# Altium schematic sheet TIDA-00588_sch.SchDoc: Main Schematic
size 431 x 279 mm; Date: Not shown in title block; ApprovedBy: Not shown in title block; CheckedBy: Not shown in title block; Author: Not shown in title block; CompanyName: Not shown in title block; DrawnBy: Gordon Varney; Engineer: Gordon Varney; Organization: Not shown in title block; Address1: Not shown in title block; Address2: Not shown in title block; Address3: Not shown in title block; Address4: Not shown in title block; DocumentNumber: 1; Revision: Use project parameter SCH_Rev; SheetNumber: 2; SheetTotal: 3; PageSetup: Record=PageOptions¦CenterHorizontal=True¦CenterVertical=True¦PrintScale=0.64¦XCorrection=1.00¦YCorrection=1.00¦PrintKind=0¦BorderSize=5000000¦LeftOffset=0¦BottomOffset=0¦Orientation=2¦PaperLength=1000¦PaperWidth=1000¦Scale=100¦PaperSource=15¦PrintQuality=600¦MediaType=1¦DitherType=10¦PrintScaleMode=1¦PaperKind=Letter
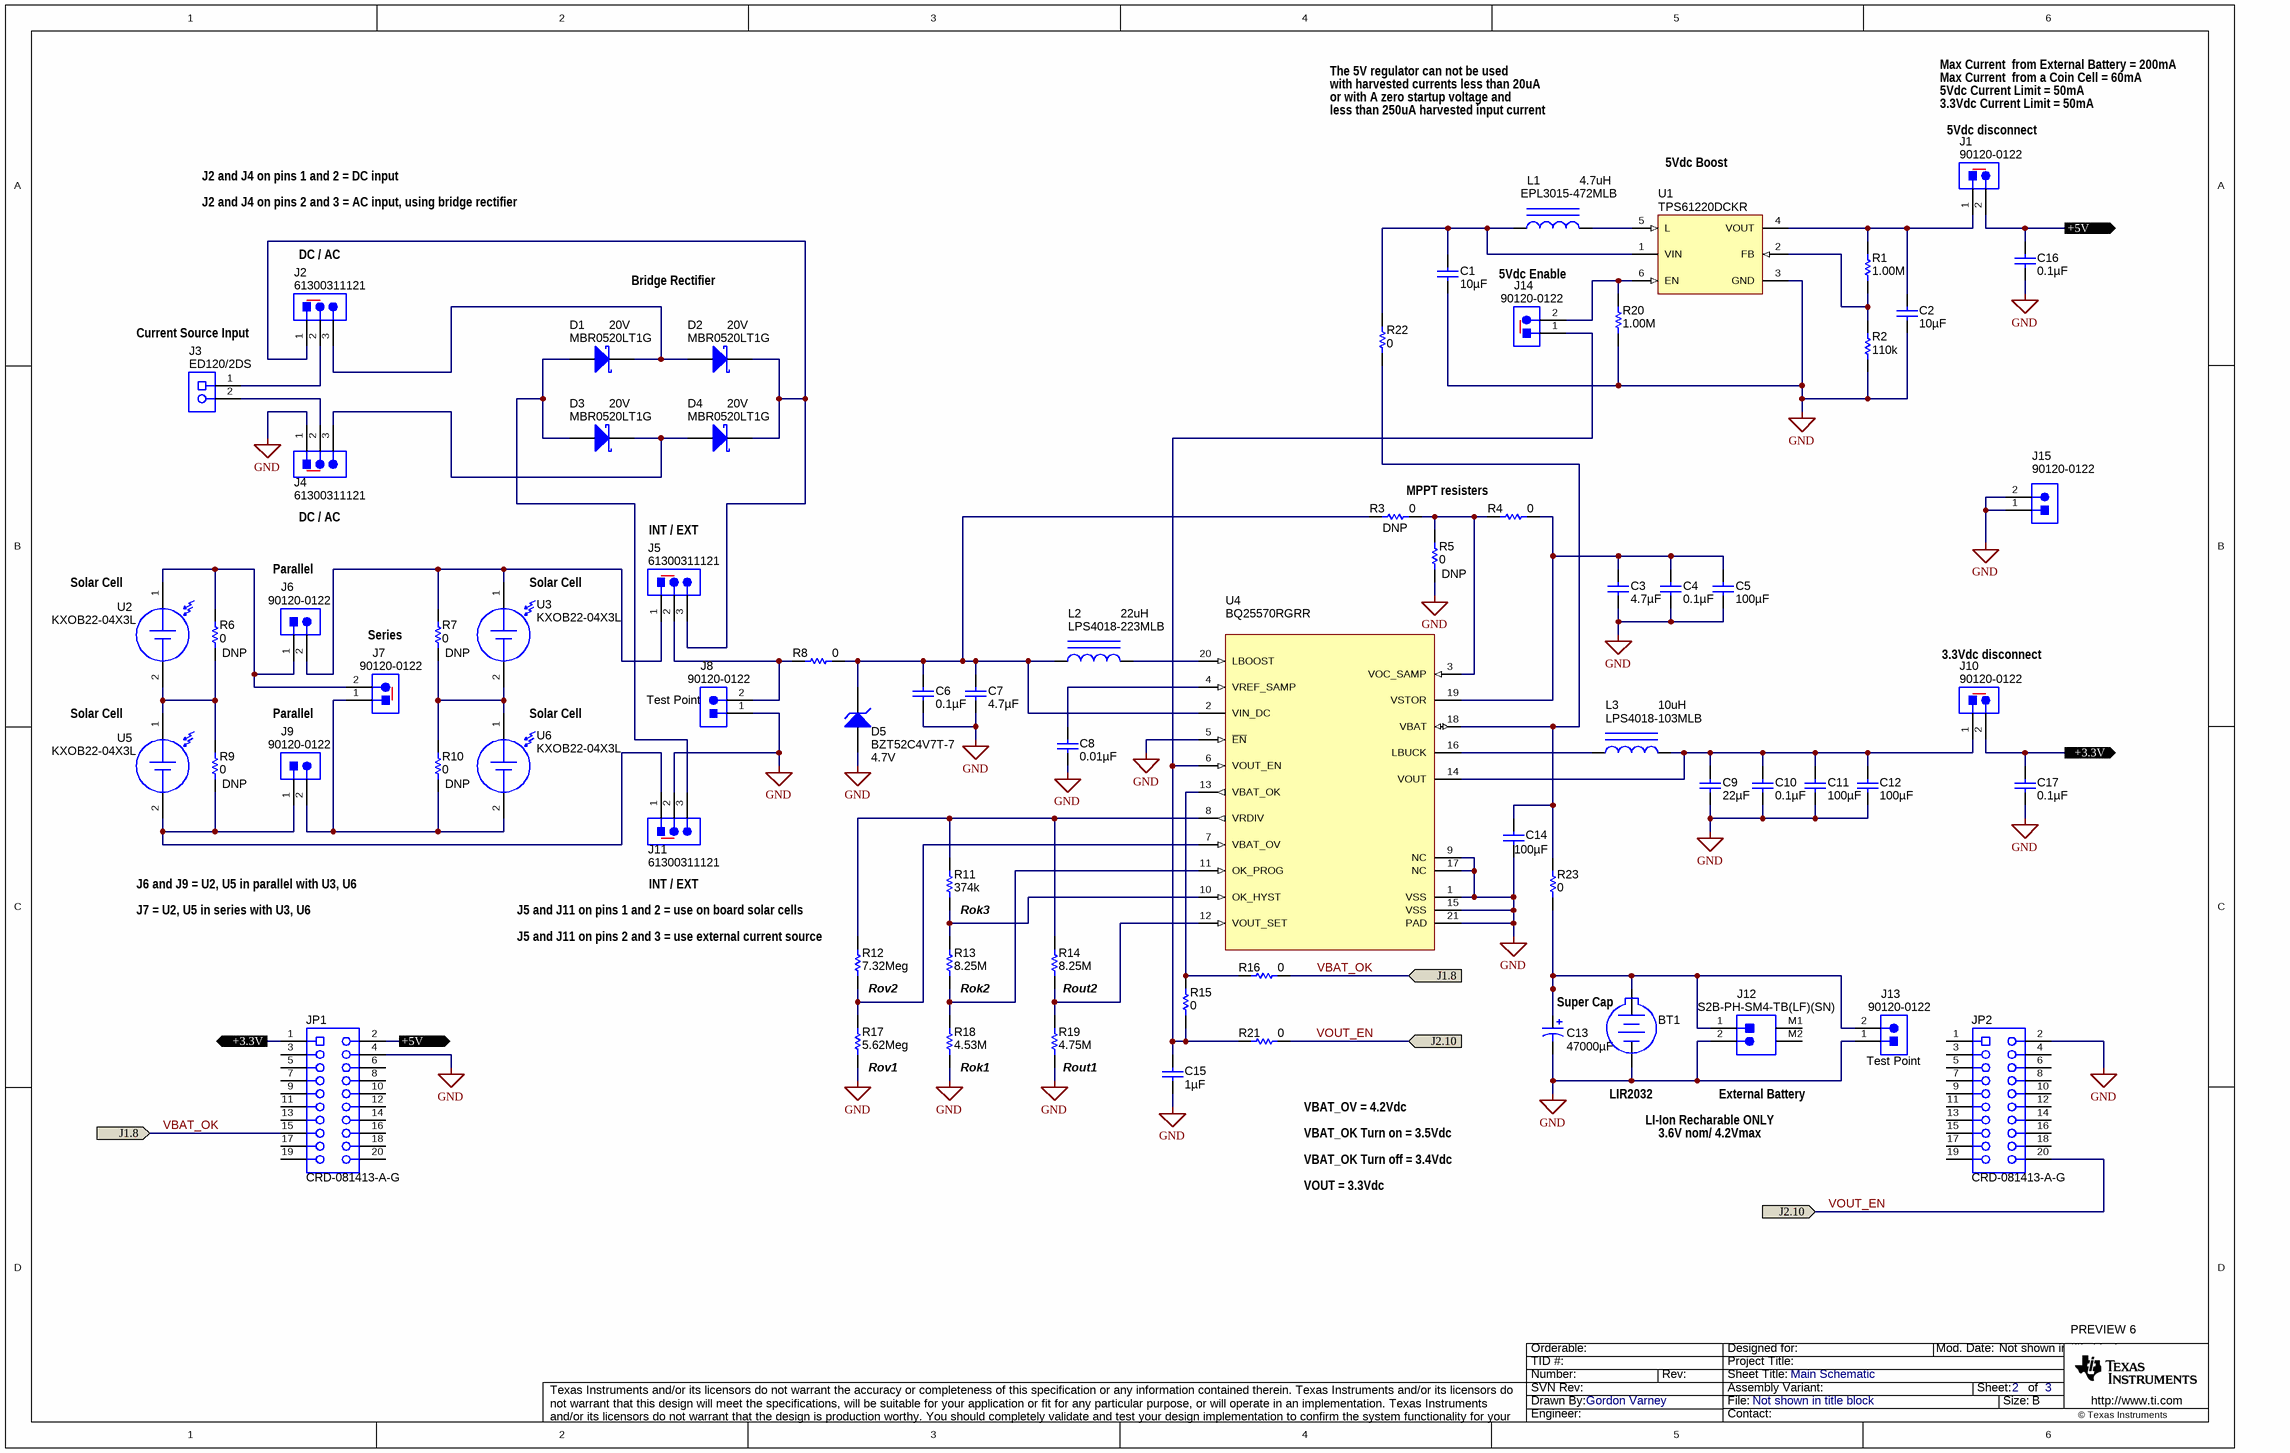
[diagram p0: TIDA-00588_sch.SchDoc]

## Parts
BT1  BS-7  [BAT_BS-7]  (value not drawn)
C1  ValueDisplayed: 10µF  [0805_HV]  (hidden comment: GRM21BR61A106KE19L)
C2  ValueDisplayed: 10µF  [0805_HV]  (hidden comment: GRM21BR61A106KE19L)
C3  ValueDisplayed: 4.7µF  [0402]  (hidden comment: C1005X5R0J475M050BC)
C4  ValueDisplayed: 0.1µF  [0402]  (hidden comment: GRM155R71A104KA01D)
C5  ValueDisplayed: 100µF  [1210]  (hidden comment: C1210C107M9PACTU)
C6  ValueDisplayed: 0.1µF  [0402]  (hidden comment: GRM155R71A104KA01D)
C7  ValueDisplayed: 4.7µF  [0402]  (hidden comment: C1005X5R0J475M050BC)
C8  ValueDisplayed: 0.01µF  [0402]  (hidden comment: GRM155R61A103KA01D)
C9  ValueDisplayed: 22µF  [0603]  (hidden comment: CL10A226MP8NUNE)
C10  ValueDisplayed: 0.1µF  [0402]  (hidden comment: GRM155R71A104KA01D)
C11  ValueDisplayed: 100µF  [1210]  (hidden comment: C1210C107M9PACTU)
C12  ValueDisplayed: 100µF  [1210]  (hidden comment: C1210C107M9PACTU)
C13  ValueDisplayed: 47000µF  [DX-H_1150x500]  (hidden comment: DX-5R5H473U)
C14  ValueDisplayed: 100µF  [1210]  (hidden comment: C1210C107M9PACTU)
C15  ValueDisplayed: 1µF  [0402]  (hidden comment: C1005X5R0J105M)
C16  ValueDisplayed: 0.1µF  [0402]  (hidden comment: GRM155R71A104KA01D)
C17  ValueDisplayed: 0.1µF  [0402]  (hidden comment: GRM155R71A104KA01D)
D1  MBR0520LT1G  value 20V  [SOD-123]
D2  MBR0520LT1G  value 20V  [SOD-123]
D3  MBR0520LT1G  value 20V  [SOD-123]
D4  MBR0520LT1G  value 20V  [SOD-123]
D5  BZT52C4V7T-7  value 4.7V  [SOD-523]
J1  90120-0122  [CONN_90120-0122]
J2  61300311121  [WURTH_61300311121]
J3  ED120/2DS  [CONN_ED120-2DS]
J4  61300311121  [WURTH_61300311121]
J5  61300311121  [WURTH_61300311121]
J6  90120-0122  [CONN_90120-0122]
J7  90120-0122  [CONN_90120-0122]
J8  90120-0122  [CONN_90120-0122]
J9  90120-0122  [CONN_90120-0122]
J10  90120-0122  [CONN_90120-0122]
J11  61300311121  [WURTH_61300311121]
J12  S2B-PH-SM4-TB(LF)(SN)  [JST_S2B-PH-SM4-TB]
J13  90120-0122  [CONN_90120-0122]
J14  90120-0122  [CONN_90120-0122]
J15  90120-0122  [CONN_90120-0122]
JP1  CRD-081413-A-G  [Major_CRD-081413-A-x]
JP2  CRD-081413-A-G  [Major_CRD-081413-A-x]
L1  EPL3015-472MLB  value 4.7uH  [EPL3015]
L2  LPS4018-223MLB  value 22uH  [LPS4018]
L3  LPS4018-103MLB  value 10uH  [LPS4018]
R1  ValueDisplayed: 1.00M  [0603]  (hidden comment: CRCW06031M00FKEA)
R2  ValueDisplayed: 110k  [0603]  (hidden comment: CRCW0603110KFKEA)
R3  value 0  Res_ohm: DNP  [0603]  (hidden comment: ERJ-3GEY0R00V)
R4  value 0  [0603]  (hidden comment: ERJ-3GEY0R00V)
R5  value 0  Res_ohm: DNP  [0603]  (hidden comment: ERJ-3GEY0R00V)
R6  value 0  ValueDisplayed: DNP  [0805_HV]  (hidden comment: CRCW08050000Z0EA)
R7  value 0  ValueDisplayed: DNP  [0805_HV]  (hidden comment: CRCW08050000Z0EA)
R8  value 0  [0603]  (hidden comment: ERJ-3GEY0R00V)
R9  value 0  ValueDisplayed: DNP  [0805_HV]  (hidden comment: CRCW08050000Z0EA)
R10  value 0  ValueDisplayed: DNP  [0805_HV]  (hidden comment: CRCW08050000Z0EA)
R11  ValueDisplayed: 374k  [0603]  (hidden comment: CRCW0603374KFKEA)
R12  value 7.32Meg  [0603]  (hidden comment: CRCW06037M32FKEA)
R13  ValueDisplayed: 8.25M  [0603]  (hidden comment: CRCW06038M25FKEA)
R14  ValueDisplayed: 8.25M  [0603]  (hidden comment: CRCW06038M25FKEA)
R15  value 0  [0603]  (hidden comment: ERJ-3GEY0R00V)
R16  value 0  [0603]  (hidden comment: ERJ-3GEY0R00V)
R17  value 5.62Meg  [0603]  (hidden comment: CRCW06035M62FKEA)
R18  ValueDisplayed: 4.53M  [0603]  (hidden comment: CRCW06034M53FKEA)
R19  ValueDisplayed: 4.75M  [0603]  (hidden comment: CRCW06034M75FKEA)
R20  ValueDisplayed: 1.00M  [0603]  (hidden comment: CRCW06031M00FKEA)
R21  value 0  [0603]  (hidden comment: ERJ-3GEY0R00V)
R22  value 0  [0603]  (hidden comment: ERJ-3GEY0R00V)
R23  value 0  [0603]  (hidden comment: ERJ-3GEY0R00V)
U1  TPS61220DCKR  [DCK0006A_N]
U2  KXOB22-04X3L  [KXOB22-04X3]
U3  KXOB22-04X3L  [KXOB22-04X3]
U4  BQ25570RGRR  [RGR0020A]
U5  KXOB22-04X3L  [KXOB22-04X3]
U6  KXOB22-04X3L  [KXOB22-04X3]

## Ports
+3.3V, +5V, J1.8, J2.10

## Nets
GND: BT1.2(-) C1.1 C2.2 C3.2 C4.2 C5.2 C6.2 C7.2 C8.2 C9.2 C10.2 C11.2 C12.2 C13.2(-) C14.2 C15.2 C16.2 C17.2 D5.2(A) J4.1 J8.1 J11.2 J12.2 J13.1 J15.1 J15.2 JP1.4 JP2.2 R2.1 R5.1 R17.1 R18.1 R19.2 R20.1 U1.3(GND) U4.1(VSS) U4.5(~{EN}) U4.9(NC) U4.15(VSS) U4.17(NC) U4.21(PAD)
+3.3V: C17.1 J10.2 JP1.1 ; port +3.3V
+5V: C16.1 J1.2 JP1.2 ; port +5V
VBAT_OK: JP1.15 R16.2 ; port J1.8
VOUT_EN: JP2.20 R21.2 ; port J2.10
NetBT1_1: BT1.1(+) C13.1(+) J12.1 J13.2 R23.1
NetC1_2: C1.2 L1.1 R22.2 U1.1(VIN)
NetC2_1: C2.1 J1.1 R1.2 U1.4(VOUT)
NetC3_1: C3.1 C4.1 C5.1 R4.2 U4.19(VSTOR)
NetC6_1: C6.1 C7.1 D5.1(K) L2.1 R3.1 R8.2 U4.2(VIN_DC)
NetC8_1: C8.1 U4.4(VREF_SAMP)
NetC9_1: C9.1 C10.1 C11.1 C12.1 J10.1 L3.2 U4.14(VOUT)
NetC14_1: C14.1 R22.1 R23.2 U4.18(VBAT)
NetC15_1: C15.1 J14.1 R15.1 R21.1 U4.6(VOUT_EN)
NetD1_1: D1.1(K) D2.2(A) J2.3
NetD1_2: D1.2(A) D3.2(A) J11.3
NetD2_1: D2.1(K) D4.1(K) J2.1 J5.3
NetD3_1: D3.1(K) D4.2(A) J4.3
NetJ2_2: J2.2 J3.1
NetJ3_2: J3.2 J4.2
NetJ5_1: J5.1 J6.2 R7.2 U3.1(+)
NetJ5_2: J5.2 J8.2 R8.1
NetJ6_1: J6.1 J7.2 R6.2 U2.1(+)
NetJ7_1: J7.1 J9.2 R10.1 U6.2(-)
NetJ9_1: J9.1 J11.1 R9.1 U5.2(-)
NetJ14_2: J14.2 R20.2 U1.6(EN)
NetL1_2: L1.2 U1.5(L)
NetL2_2: L2.2 U4.20(LBOOST)
NetL3_1: L3.1 U4.16(LBUCK)
NetR1_1: R1.1 R2.2 U1.2(FB)
NetR3_2: R3.2 R4.1 R5.2 U4.3(VOC_SAMP)
NetR6_1: R6.1 R9.2 U2.2(-) U5.1(+)
NetR7_1: R7.1 R10.2 U3.2(-) U6.1(+)
NetR11_1: R11.1 R13.2 U4.10(OK_HYST)
NetR11_2: R11.2 R12.2 R14.2 U4.8(VRDIV)
NetR12_1: R12.1 R17.2 U4.7(VBAT_OV)
NetR13_1: R13.1 R18.2 U4.11(OK_PROG)
NetR14_1: R14.1 R19.1 U4.12(VOUT_SET)
NetR15_2: R15.2 R16.1 U4.13(VBAT_OK)

Not connected (* = marked no-connect by the designer): J12 M1 M2; JP1 3 5 6 7 8 9 10 11 12 13 14 16 17 18 19 20; JP2 1 3 4 5 6 7 8 9 10 11 12 13 14 15 16 17 18 19

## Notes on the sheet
- with harvested currents less than 20uA
- The 5V regulator can not be used
- or with A zero startup voltage and
- Max Current  from External Battery = 200mA
- 5Vdc Current Limit = 50mA
- Max Current  from a Coin Cell = 60mA
- less than 250uA harvested input current
- 5Vdc Boost
- 3.3Vdc Current Limit = 50mA
- (near J1) 5Vdc disconnect
- J2 and J4 on pins 1 and 2 = DC input
- J2 and J4 on pins 2 and 3 = AC input, using bridge rectifier
- DC / AC
- Bridge Rectifier
- 5Vdc Enable
- Current Source Input
- MPPT resisters
- INT / EXT
- (near U2) Solar Cell
- Parallel
- (near U3) Solar Cell
- Series
- (near J10) 3.3Vdc disconnect
- Solar Cell
- (near U6) Solar Cell
- (near J8) Test Point
- J6 and J9 = U2, U5 in parallel with U3, U6
- J7 = U2, U5 in series with U3, U6
- (near R12) J5 and J11 on pins 1 and 2 = use on board solar cells
- (near R12) J5 and J11 on pins 2 and 3 = use external current source
- (near R11) Rok3
- (near R12) Rov2
- (near R13) Rok2
- (near R14) Rout2
- Super Cap
- (near R17) Rov1
- (near R18) Rok1
- (near R19) Rout1
- (near J13) Test Point
- VBAT_OV = 4.2Vdc
- VBAT_OK Turn on = 3.5Vdc
- LIR2032
- LI-Ion Recharable ONLY
- 3.6V nom/ 4.2Vmax
- (near J12) External Battery
- VBAT_OK Turn off = 3.4Vdc
- VOUT = 3.3Vdc
- PREVIEW 6

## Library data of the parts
BT1 = BS-7: Battery Holder, CR2032, Retainer clip, TH; Manufacturer: Memory Protection Devices; SymbolCreator: a0412235
C1 C2 = GRM21BR61A106KE19L: CAP, CERM, 10 µF, 10 V, +/- 10%, X5R, 0805; Manufacturer: MuRata; Polarized: N; CompType: Capacitor; Value: 10uF; U/M: EA; Cap_F: 0.00001; Tolerance_%: 10; ESR_ohm: 0.002; Value1: 0.002 ohm; Value2: 10V; TaMin_C: -55; TaMax_C: 85; Cap_Case: 0805
C3 C7 = C1005X5R0J475M050BC: CAP, CERM, 4.7 µF, 6.3 V, +/- 20%, X5R, 0402; Manufacturer: TDK; Polarized: N; CompType: Capacitor; Value: 4.7uF; U/M: EA; Cap_F: 0.0000047; Tolerance_%: 20; Value1: Unknown; VDC_V: 6.3; Value2: 6.3V; TaMin_C: -55; TaMax_C: 85
C4 C6 C10 C16 C17 = GRM155R71A104KA01D: CAP, CERM, 0.1 µF, 10 V, +/- 10%, X7R, 0402; Manufacturer: MuRata; Polarized: N; CompType: Capacitor; Value: 0.1uF; U/M: EA; Cap_F: 0.0000001; Tolerance_%: 10; Value1: Unknown; Value2: 10V; TaMin_C: -55; TaMax_C: 125
C5 C11 C12 C14 = C1210C107M9PACTU: CAP, CERM, 100 µF, 6.3 V, +/- 20%, X5R, 1210; Manufacturer: Kemet; Polarized: N; CompType: Capacitor; Value: 100uF; U/M: EA; Cap_F: 0.0001; Tolerance_%: 20; Value1: Unknown; VDC_V: 6.3; Value2: 6.3V; TaMin_C: -55; TaMax_C: 85
C8 = GRM155R61A103KA01D: CAP, CERM, 0.01 µF, 10 V, +/- 10%, X5R, 0402; Manufacturer: MuRata; Polarized: N; CompType: Capacitor; Value: 0.01uF; U/M: EA; Cap_F: 0.00000001; Tolerance_%: 10; Value1: Unknown; Value2: 10V; TaMin_C: -55; TaMax_C: 85
C9 = CL10A226MP8NUNE: CAP, CERM, 22 µF, 10 V, +/- 20%, X5R, 0603; Manufacturer: Samsung Electro-Mechanics; Polarized: N; CompType: Capacitor; Value: 22uF; U/M: EA; Cap_F: 0.000022; Tolerance_%: 20; Value1: Unknown; VDC_V: 10; Value2: 10V; TaMin_C: -55; TaMax_C: 85
C13 = DX-5R5H473U: CAP, Electric Double Layer, 47000 µF, 5.5 V, +80/-20%, TH; Manufacturer: Elna; Polarized: Y; CompType: Capacitor; Value: 47000uF; U/M: EA; Cap_F: 0.047; Tolerance_%: 80; Value1: Unknown; VDC_V: 5.5; Value2: 5.5V; TaMin_C: -25; TaMax_C: 70
C15 = C1005X5R0J105M: CAP, CERM, 1 µF, 6.3 V, +/- 20%, X5R, 0402; Manufacturer: TDK; Polarized: N; CompType: Capacitor; Value: 1uF; U/M: EA; Cap_F: 0.000001; Tolerance_%: 20; ESR_ohm: 0.0079; Value1: 0.0079 ohm; VDC_V: 6.3; Value2: 6.3V; TaMin_C: -55; TaMax_C: 85
D1-D4 = MBR0520LT1G: Diode, Schottky, 20 V, 0.5 A, SOD-123; Manufacturer: ON Semiconductor; U/M: EA; Vf_V: 0.385; Value1: 0.5A; Value2: 0.385V; Io_A: 0.5; Vr_V: 20; TJmax_C: 125; RJC_CperW: 150
D5 = BZT52C4V7T-7: Diode, Zener, 4.7 V, 300 mW, SOD-523; Manufacturer: Diodes Inc.; U/M: EA; Power_W: 0.3; Vz_V: 4.7; Value1: 0.3W; RJA_CperW: 417; SymbolCreator: a0412235
J1 J6-J10 J13-J15 = 90120-0122: Header, 100mil, 2x1, Tin, TH; Manufacturer: Molex; SymbolCreator: a0412235; U/M: EA
J2 J4 J5 J11 = 61300311121: Header, 2.54 mm, 3x1, Gold, TH; Manufacturer: Wurth Elektronik; SymbolCreator: a0799628; U/M: EA
J3 = ED120/2DS: TERMINAL BLOCK 5.08MM VERT 2POS, TH; Manufacturer: On-Shore Technology; SymbolCreator: a0412235; U/M: EA
J12 = S2B-PH-SM4-TB(LF)(SN): Header (shrouded), 2mm, 2x1, R/A, SMT; Manufacturer: JST Manufacturing; SymbolCreator: x0208326; U/M: EA
JP1 JP2 = CRD-081413-A-G: Receptacle, 2.54 mm, 10x2, Gold, TH; Manufacturer: Major League Electronics; SymbolCreator: a0412235; U/M: EA
L1 = EPL3015-472MLB: Inductor, Shielded, Ferrite, 4.7 µH, 1.2 A, 0.14 ohm, SMD; Manufacturer: Coilcraft; Ind_H: 4.7E-6; ValueDisplayed: 4.7µH; Imax_A: 1.2; Irms: 1.4A @ 40C rise; Isat: 1.2A @ 30% inductance drop; DCR_ohm: 0.14; Value2: 1.2A
L2 = LPS4018-223MLB: Inductor, Shielded Drum Core, Ferrite, 22 µH, 0.83 A, 0.36 ohm, SMD; Manufacturer: Coilcraft; Ind_H: 22.0E-6; ValueDisplayed: 22µH; Imax_A: 0.83; Irms: 0.9A @ 40C rise; Isat: 0.83A @ 30% inductance drop; DCR_ohm: 0.36; Value2: 0.83A
L3 = LPS4018-103MLB: Inductor, Shielded Drum Core, Ferrite, 10 µH, 1.25 A, 0.2 ohm, SMD; Manufacturer: Coilcraft; Ind_H: 10.0E-6; ValueDisplayed: 10µH; Imax_A: 1.25; Irms: 1.25A @ 40C rise; Isat: 1.3A @ 30% inductance drop; DCR_ohm: 0.2; Value1: 0.2 ohm; Value2: 1.25A
R1 R20 = CRCW06031M00FKEA: RES, 1.00 M, 1%, 0.1 W, 0603; Manufacturer: Vishay-Dale; CompType: Resistor; Value: 1.00Meg; Res_ohm: 1000000; Value_Code: 1M00; Tolerance_%: 1; Power_W: 0.1; Value2: 0.1W; VDC_V: 75; TempCo: 100 ppm/C; EIA_Code: E96; U/M: EA
R2 = CRCW0603110KFKEA: RES, 110 k, 1%, 0.1 W, 0603; Manufacturer: Vishay-Dale; CompType: Resistor; Value: 110k; Res_ohm: 110000; Tolerance_%: 1; Power_W: 0.1; Value2: 0.1W; VDC_V: 75; TempCo: 100 ppm/C; EIA_Code: E96; U/M: EA
R3-R5 R8 R15 R16 R21-R23 = ERJ-3GEY0R00V: RES, 0, 5%, 0.1 W, 0603; Manufacturer: Panasonic; CompType: Resistor; Value_Code: 0000; Tolerance_%: 5; Power_W: 0.1; Value2: 0.1W; VDC_V: 50; TempCo: 600 ppm/C; EIA_Code: E24; U/M: EA
R6 R7 R9 R10 = CRCW08050000Z0EA: RES, 0, 5%, 0.125 W, 0805; Manufacturer: Vishay-Dale; CompType: Resistor; Value_Code: 0000; Tolerance_%: 5; Power_W: 0.125; Value2: 0.125W; VDC_V: 150; TempCo: 200 ppm/C; EIA_Code: E24; U/M: EA
R11 = CRCW0603374KFKEA: RES, 374 k, 1%, 0.1 W, 0603; Manufacturer: Vishay-Dale; CompType: Resistor; Value: 374k; Res_ohm: 374000; Tolerance_%: 1; Power_W: 0.1; Value2: 0.1W; VDC_V: 75; TempCo: 100 ppm/C; EIA_Code: E96; U/M: EA
R12 = CRCW06037M32FKEA: RES, 7.32 M, 1%, 0.1 W, 0603; Manufacturer: Vishay-Dale; CompType: Resistor; Res_ohm: 7320000; Value_Code: 7M32; Tolerance_%: 1; Power_W: 0.1; Value2: 0.1W; VDC_V: 75; TempCo: 100 ppm/C; EIA_Code: E96; U/M: EA
R13 R14 = CRCW06038M25FKEA: RES, 8.25 M, 1%, 0.1 W, 0603; Manufacturer: Vishay-Dale; CompType: Resistor; Value: 8.25Meg; Res_ohm: 8250000; Value_Code: 8M25; Tolerance_%: 1; Power_W: 0.1; Value2: 0.1W; VDC_V: 75; TempCo: 100 ppm/C; EIA_Code: E96; U/M: EA
R17 = CRCW06035M62FKEA: RES, 5.62 M, 1%, 0.1 W, 0603; Manufacturer: Vishay-Dale; CompType: Resistor; Res_ohm: 5620000; Value_Code: 5M62; Tolerance_%: 1; Power_W: 0.1; Value2: 0.1W; VDC_V: 75; TempCo: 100 ppm/C; EIA_Code: E96; U/M: EA
R18 = CRCW06034M53FKEA: RES, 4.53 M, 1%, 0.1 W, 0603; Manufacturer: Vishay-Dale; CompType: Resistor; Value: 4.53Meg; Res_ohm: 4530000; Value_Code: 4M53; Tolerance_%: 1; Power_W: 0.1; Value2: 0.1W; VDC_V: 75; TempCo: 100 ppm/C; EIA_Code: E96; U/M: EA
R19 = CRCW06034M75FKEA: RES, 4.75 M, 1%, 0.1 W, 0603; Manufacturer: Vishay-Dale; CompType: Resistor; Value: 4.75Meg; Res_ohm: 4750000; Value_Code: 4M75; Tolerance_%: 1; Power_W: 0.1; Value2: 0.1W; VDC_V: 75; TempCo: 100 ppm/C; EIA_Code: E96; U/M: EA
U1 = TPS61220DCKR: LOW INPUT VOLTAGE STEP-UP CONVERTER IN 6 PIN SC-70 PACKAGE, DCK0006A; Alternate PartNumber: TPS61220DCKT; Manufacturer: Texas Instruments; SymbolCreator: a0799628; CompType: IC; U/M: EA
U2 U3 U5 U6 = KXOB22-04X3L: MONOCRYSTALLINE SOLAR CELL, 22MM X 7MM, SMD; Manufacturer: IXYS; SymbolCreator: a0412235; Value: 1.5V
U4 = BQ25570RGRR: Ultra Low Power Harvester Power Management IC with Boost Charger, and Nano-Powered Buck Converter, RGR0020A; Alternate PartNumber: BQ25570RGRT; Manufacturer: Texas Instruments; SymbolCreator: a0412235; U/M: EA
